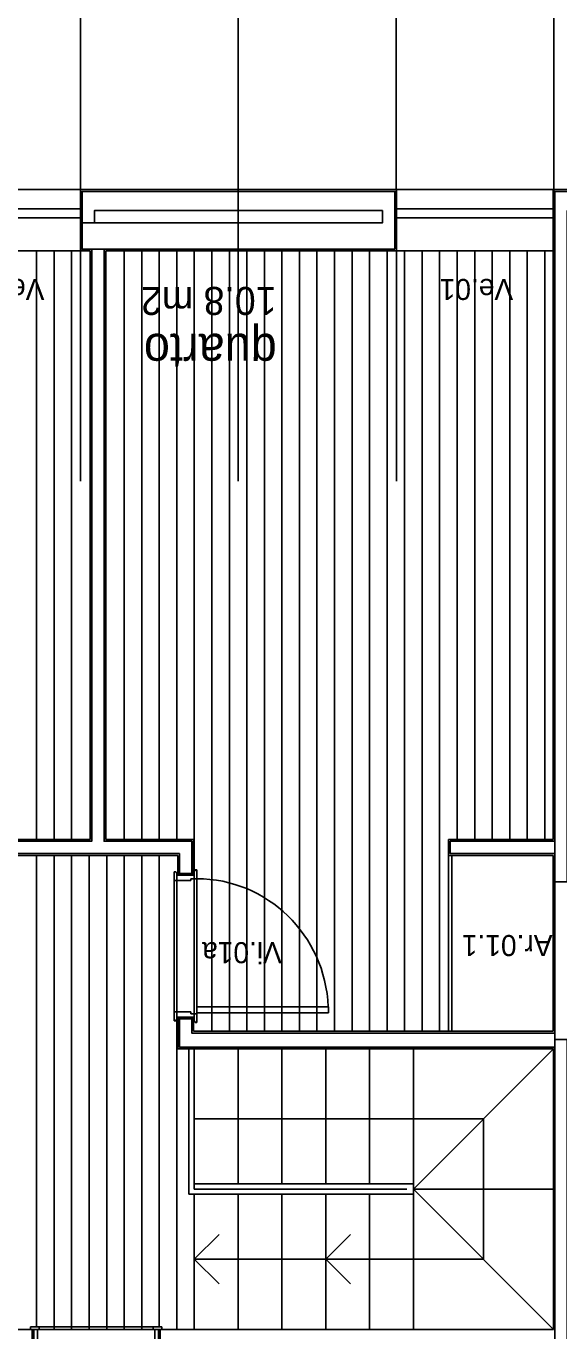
# Model space of a CAD drawing. Extents: x 1278 to 1356, y -253.7 to -224.
# Drawn here: x 1320.78 to 1323.82, y -238.43 to -230.99 of the extents above; entities that cross this region are included whole.
import ezdxf

# ---------------------------------------------------------------- set-up
doc = ezdxf.new("R2010")
doc.units = 0
for name, color, linetype in [('Level 1', 7, 'Continuous'), ('Level 10', 7, 'Continuous'), ('Level 13', 7, 'Continuous'), ('Level 2', 7, 'Continuous'), ('Level 4', 7, 'Continuous'), ('Level 40', 7, 'Continuous'), ('Level 60', 7, 'Continuous'), ('Level 62', 7, 'Continuous'), ('Level 65', 7, 'Continuous'), ('Level 66', 7, 'Continuous'), ('Level 67', 7, 'Continuous'), ('Level 93', 7, 'Continuous')]:
    doc.layers.add(name, color=color, linetype=linetype)

msp = doc.modelspace()

# ---------------------------------------------------------------- linework, layer by layer
at = {"layer": 'Level 1'}
for p, q in [((1321.1033, -232.264), (1321.1033, -231.934)), ((1321.1033, -231.934), (1322.887, -231.934)), ((1322.887, -231.934), (1322.887, -232.264)), ((1321.1733, -232.1143), (1321.1733, -232.044)), ((1322.817, -232.044), (1322.817, -232.1143)), ((1322.887, -232.264), (1321.1033, -232.264)), ((1321.1583, -232.264), (1321.1583, -235.6407)), ((1321.2283, -235.6407), (1321.2283, -232.264)), ((1321.1583, -235.6407), (1320.6583, -235.6407)), ((1321.7283, -235.6407), (1321.2283, -235.6407)), ((1321.7283, -235.824), (1321.7283, -235.6407)), ((1323.2033, -235.7107), (1323.2033, -235.6407)), ((1323.2033, -235.6407), (1323.801, -235.6407)), ((1320.7283, -235.7107), (1321.6583, -235.7107)), ((1321.6583, -235.7107), (1321.6583, -235.824)), ((1323.801, -235.7107), (1323.2033, -235.7107)), ((1321.7433, -235.824), (1321.6433, -235.824)), ((1321.7433, -236.654), (1321.6433, -236.654)), ((1321.6583, -236.814), (1321.6583, -236.654)), ((1321.7283, -236.654), (1321.7283, -236.734)), ((1321.7283, -236.734), (1323.801, -236.734)), ((1323.801, -236.814), (1321.6583, -236.814)), ((1320.8183, -238.529), (1320.8183, -238.424)), ((1321.5483, -238.529), (1321.5483, -238.424))]:
    msp.add_line(p, q, dxfattribs=at)
at = {"layer": 'Level 10'}
for p, q in [((1320.8433, -232.274), (1320.8433, -235.6307)), ((1320.9433, -232.274), (1320.9433, -235.6307)), ((1321.0433, -232.274), (1321.0433, -235.6307)), ((1321.3433, -235.6307), (1321.3433, -232.274)), ((1321.4433, -235.6307), (1321.4433, -232.274)), ((1321.5433, -235.6307), (1321.5433, -232.274)), ((1321.6433, -235.6307), (1321.6433, -232.274)), ((1321.7433, -235.809), (1321.7433, -232.274)), ((1321.8433, -232.274), (1321.8433, -236.724)), ((1321.9433, -232.274), (1321.9433, -236.724)), ((1322.0433, -232.274), (1322.0433, -236.724)), ((1322.1433, -232.274), (1322.1433, -236.724)), ((1322.2433, -232.274), (1322.2433, -236.724)), ((1322.3433, -232.274), (1322.3433, -236.724)), ((1322.4433, -232.274), (1322.4433, -236.724)), ((1322.5433, -232.274), (1322.5433, -236.724)), ((1322.6433, -232.274), (1322.6433, -236.724)), ((1322.7433, -232.274), (1322.7433, -236.724)), ((1322.8433, -232.274), (1322.8433, -236.724)), ((1322.9433, -232.274), (1322.9433, -236.724)), ((1323.0433, -232.274), (1323.0433, -236.724)), ((1323.1433, -232.274), (1323.1433, -236.724)), ((1323.2433, -232.274), (1323.2433, -235.6307)), ((1323.3433, -232.274), (1323.3433, -235.6307)), ((1323.4433, -232.274), (1323.4433, -235.6307)), ((1323.5433, -232.274), (1323.5433, -235.6307)), ((1323.6433, -232.274), (1323.6433, -235.6307)), ((1323.7433, -232.274), (1323.7433, -235.6307)), ((1320.8433, -235.7207), (1320.8433, -238.409)), ((1320.9433, -235.7207), (1320.9433, -238.424)), ((1321.0433, -235.7207), (1321.0433, -238.424)), ((1321.1433, -235.7207), (1321.1433, -238.424)), ((1321.2433, -235.7207), (1321.2433, -238.424)), ((1321.3433, -235.7207), (1321.3433, -238.424)), ((1321.4433, -235.7207), (1321.4433, -238.424)), ((1321.5433, -235.7207), (1321.5433, -238.409)), ((1321.6433, -235.864), (1321.6433, -236.614)), ((1321.7433, -235.854), (1321.7433, -236.624)), ((1321.6433, -236.659), (1321.6433, -238.424)), ((1321.5083, -238.424), (1320.8583, -238.424))]:
    msp.add_line(p, q, dxfattribs=at)
at = {"layer": 'Level 13'}
for p, q in [((1323.1933, -236.724), (1323.1933, -235.7207)), ((1323.2133, -236.724), (1323.2133, -235.7207)), ((1321.6283, -235.814), (1321.6283, -235.864)), ((1321.6383, -235.814), (1321.6283, -235.814)), ((1321.6383, -235.819), (1321.6383, -235.814)), ((1321.6433, -235.819), (1321.6383, -235.819)), ((1321.6433, -235.864), (1321.6433, -235.819)), ((1321.7433, -235.854), (1321.7433, -235.809)), ((1321.7433, -235.809), (1321.7483, -235.809)), ((1321.7483, -235.809), (1321.7483, -235.804)), ((1321.7483, -235.804), (1321.7583, -235.804)), ((1321.7583, -235.804), (1321.7583, -235.854)), ((1321.6283, -235.864), (1321.6433, -235.864)), ((1321.7433, -235.834), (1321.6433, -235.834)), ((1321.6433, -235.834), (1321.6433, -235.864)), ((1321.6433, -235.864), (1321.7233, -235.864)), ((1321.7233, -235.864), (1321.7233, -235.854)), ((1321.7233, -235.854), (1321.7433, -235.854)), ((1321.7433, -235.854), (1321.7433, -235.834)), ((1321.7583, -235.854), (1321.7433, -235.854)), ((1321.6283, -236.664), (1321.6283, -236.614)), ((1321.6283, -236.614), (1321.6433, -236.614)), ((1321.6433, -236.614), (1321.6433, -236.659)), ((1321.6433, -236.644), (1321.6433, -236.614)), ((1321.6433, -236.614), (1321.7233, -236.614)), ((1321.7233, -236.614), (1321.7233, -236.624)), ((1321.7233, -236.624), (1321.7433, -236.624)), ((1321.7433, -236.624), (1321.7433, -236.644)), ((1321.7583, -236.624), (1321.7433, -236.624)), ((1321.7433, -236.624), (1321.7433, -236.669)), ((1321.7583, -236.619), (1321.7583, -236.584)), ((1321.7583, -236.584), (1322.5083, -236.584)), ((1322.5083, -236.619), (1321.7583, -236.619)), ((1321.7583, -236.674), (1321.7583, -236.624)), ((1322.5083, -236.584), (1322.5083, -236.619)), ((1321.6383, -236.664), (1321.6283, -236.664)), ((1321.6433, -236.659), (1321.6383, -236.659)), ((1321.6383, -236.659), (1321.6383, -236.664)), ((1321.7433, -236.644), (1321.6433, -236.644)), ((1321.7433, -236.669), (1321.7483, -236.669)), ((1321.7483, -236.669), (1321.7483, -236.674)), ((1321.7483, -236.674), (1321.7583, -236.674)), ((1320.8083, -238.409), (1320.8583, -238.409)), ((1320.8083, -238.424), (1320.8083, -238.409)), ((1320.8583, -238.424), (1320.8083, -238.424)), ((1320.8283, -238.529), (1320.8283, -238.424)), ((1320.8283, -238.424), (1320.8583, -238.424)), ((1320.8483, -238.424), (1320.8483, -238.529)), ((1320.8583, -238.409), (1320.8583, -238.424)), ((1321.5583, -238.409), (1321.5083, -238.409)), ((1321.5083, -238.409), (1321.5083, -238.424)), ((1321.5383, -238.424), (1321.5083, -238.424)), ((1321.5083, -238.424), (1321.5583, -238.424)), ((1321.5183, -238.424), (1321.5183, -238.529)), ((1321.5383, -238.529), (1321.5383, -238.424)), ((1321.5583, -238.424), (1321.5583, -238.409))]:
    msp.add_line(p, q, dxfattribs=at)
at = {"layer": 'Level 2'}
for p, q in [((1321.0933, -231.924), (1320.1933, -231.924)), ((1323.7933, -231.924), (1322.897, -231.924)), ((1321.0933, -232.034), (1320.1933, -232.034)), ((1321.0933, -232.084), (1320.1933, -232.084)), ((1323.7933, -232.034), (1322.897, -232.034)), ((1323.7933, -232.084), (1322.897, -232.084)), ((1321.0933, -232.274), (1320.1933, -232.274)), ((1323.7933, -232.274), (1322.897, -232.274)), ((1321.7125, -237.654), (1321.7125, -236.8257)), ((1321.7425, -237.624), (1321.7425, -236.8257)), ((1321.9933, -237.594), (1321.9933, -236.824)), ((1322.2433, -237.594), (1322.2433, -236.824)), ((1322.4933, -237.594), (1322.4933, -236.824)), ((1322.7433, -237.594), (1322.7433, -236.824)), ((1322.9933, -237.594), (1322.9933, -236.824)), ((1322.9933, -237.624), (1323.7933, -236.824)), ((1321.7433, -237.224), (1323.3933, -237.224)), ((1323.3933, -238.024), (1323.3933, -237.224)), ((1322.9933, -237.594), (1321.7433, -237.594)), ((1322.9933, -237.654), (1322.9933, -237.594)), ((1322.9933, -237.654), (1321.7125, -237.654)), ((1322.9563, -237.624), (1321.7425, -237.624)), ((1321.7433, -238.424), (1321.7433, -237.654)), ((1321.9933, -238.424), (1321.9933, -237.654)), ((1322.2433, -238.424), (1322.2433, -237.654)), ((1322.4933, -237.654), (1322.4933, -238.424)), ((1322.7433, -238.424), (1322.7433, -237.654)), ((1323.7933, -237.624), (1322.9933, -237.624)), ((1322.9933, -237.624), (1323.7933, -238.424)), ((1322.9933, -238.424), (1322.9933, -237.654)), ((1321.8847, -237.8826), (1321.7433, -238.024)), ((1322.6347, -237.8826), (1322.4933, -238.024)), ((1321.8847, -238.1654), (1321.7433, -238.024)), ((1323.3933, -238.024), (1321.7433, -238.024)), ((1322.6347, -238.1654), (1322.4933, -238.024))]:
    msp.add_line(p, q, dxfattribs=at)
at = {"layer": 'Level 4'}
for p, q in [((1321.6283, -236.614), (1321.6283, -235.864)), ((1321.7583, -235.854), (1321.7583, -236.584)), ((1320.8583, -238.409), (1321.5083, -238.409))]:
    msp.add_line(p, q, dxfattribs=at)
msp.add_ellipse((1321.7583, -236.6172), major_axis=(0, -0.7632), ratio=0.982661, start_param=1.614288, end_param=3.141593, dxfattribs=at)
at = {"layer": 'Level 62'}
msp.add_line((1323.7133, -238.424), (1323.399, -238.424), dxfattribs=at)
at = {"layer": 'Level 65'}
for p, q in [((1321.0933, -232.274), (1321.0933, -231.924)), ((1321.0933, -231.924), (1322.897, -231.924)), ((1322.897, -231.924), (1322.897, -232.274)), ((1325.5918, -231.924), (1323.791, -231.924)), ((1323.791, -235.6307), (1323.791, -231.924)), ((1321.1483, -232.274), (1321.0933, -232.274)), ((1321.1483, -232.274), (1321.1483, -235.6307)), ((1322.897, -232.274), (1321.2383, -232.274)), ((1321.2383, -235.6307), (1321.2383, -232.274)), ((1321.1483, -235.6307), (1320.6483, -235.6307)), ((1321.7383, -235.6307), (1321.2383, -235.6307)), ((1321.7383, -235.824), (1321.7383, -235.6307)), ((1323.1933, -235.7207), (1323.1933, -235.6307)), ((1323.1933, -235.6307), (1323.791, -235.6307)), ((1320.7383, -235.7207), (1321.6483, -235.7207)), ((1321.6483, -235.7207), (1321.6483, -235.824)), ((1323.791, -235.7207), (1323.1933, -235.7207)), ((1323.791, -236.724), (1323.791, -235.7207)), ((1323.791, -236.724), (1323.791, -235.724)), ((1321.6483, -236.824), (1321.6483, -236.654)), ((1321.7383, -236.654), (1321.7383, -236.724)), ((1321.7383, -236.724), (1323.791, -236.724)), ((1323.7933, -236.824), (1321.6483, -236.824)), ((1323.7933, -238.424), (1323.7933, -236.824)), ((1320.816, -238.4257), (1320.7383, -238.4257)), ((1321.5483, -238.424), (1323.7933, -238.424))]:
    msp.add_line(p, q, dxfattribs=at)
at = {"layer": 'Level 66'}
for p, q in [((1325.5818, -231.934), (1323.801, -231.934)), ((1323.801, -235.6407), (1323.801, -231.934)), ((1322.817, -232.044), (1321.1733, -232.044)), ((1322.817, -232.1143), (1321.1733, -232.1143)), ((1323.801, -236.734), (1323.801, -235.7107)), ((1323.801, -238.434), (1323.801, -236.814))]:
    msp.add_line(p, q, dxfattribs=at)
msp.add_lwpolyline([(1323.801, -235.8713), (1324.031, -235.8713), (1324.031, -236.7713), (1323.801, -236.7713)], close=True, dxfattribs=at)
at = {"layer": 'Level 67'}
for points in [[(1322.887, -232.264), (1322.887, -231.934), (1321.1033, -231.934), (1321.1033, -232.1143), (1321.1733, -232.1143), (1321.1733, -232.044), (1322.817, -232.044), (1322.817, -232.1143), (1321.1033, -232.1143), (1321.1033, -232.264)], [(1323.871, -235.8713), (1323.871, -232.044), (1325.5118, -232.044), (1325.5118, -232.1143), (1323.9218, -232.1143), (1323.9218, -235.8713), (1324.031, -235.8713), (1324.0317, -232.2657), (1325.5818, -232.2657), (1325.5818, -231.934), (1323.801, -231.934), (1323.801, -235.8713)], [(1321.6583, -235.824), (1321.6583, -235.7107), (1320.7283, -235.7107), (1320.7283, -235.824), (1320.6583, -235.824), (1320.6583, -235.6407), (1321.1583, -235.6407), (1321.1583, -232.264), (1321.2283, -232.264), (1321.2283, -235.6407), (1321.7283, -235.6407), (1321.7283, -235.824)], [(1323.801, -235.6407), (1323.2033, -235.6407), (1323.2033, -235.7107), (1323.801, -235.7107)], [(1323.801, -236.734), (1323.801, -236.814), (1321.6583, -236.814), (1321.6583, -236.654), (1321.7283, -236.654), (1321.7283, -236.734)], [(1323.871, -242.1713), (1323.801, -242.1713), (1323.801, -236.7713), (1323.871, -236.7713), (1323.871, -242.1713)]]:
    msp.add_lwpolyline(points, close=True, dxfattribs=at)
at = {"layer": 'Level 93'}
for p, q in [((1321.094, -233.587), (1321.094, -228.3936)), ((1321.994, -233.587), (1321.994, -228.3936)), ((1322.897, -233.587), (1322.894, -228.3936)), ((1323.794, -233.587), (1323.794, -228.3936))]:
    msp.add_line(p, q, dxfattribs=at)

# ---------------------------------------------------------------- texts
at = {"layer": 'Level 40'}
for s, rotation, p in [('Ve.01', 180.00001, (1320.8881, -232.4333)), ('Ve.01', 180.00001, (1323.5628, -232.4333)), ('Ar.01.1', 179.99999, (1323.7873, -236.1751)), ('Vi.01a', 180.00001, (1322.2427, -236.2158))]:
    msp.add_text(s, height=0.12, rotation=rotation, dxfattribs=at).set_placement(p)
at = {"layer": 'Level 60'}
for s, height, p in [('10.8 m2', 0.16, (1322.2124, -232.4787)), ('quarto', 0.2, (1322.2137, -232.7464))]:
    msp.add_text(s, height=height, rotation=180, dxfattribs=at).set_placement(p)

doc.saveas('drawing.dxf')
